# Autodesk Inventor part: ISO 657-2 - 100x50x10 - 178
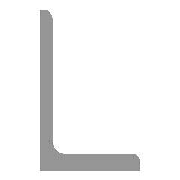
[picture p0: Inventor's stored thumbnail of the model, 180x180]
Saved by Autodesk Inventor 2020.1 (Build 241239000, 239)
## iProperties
Created: 2019-01
Part Number: ISO 657-2 - 100x50x10 - 178
Material: Stahl, weich
Description: Warm gewalzter Winkelstahl, ungleichschenklig
Document SubType Name: Modeling
Standard: ISO
Designer: lutzd
Standard Revision: First edition 1989-08-01
Standards Organization: ISO
Language: de-DE
Size Designation: 100x50x10
Categories: <MemberInstance><Categories><Category DisplayName="Profile" InternalName="089c4875-fa83-4c05-b084-43b9cc11f5ed" Mnemonic="GRDR"><CategoryParameter DisplayName="
Stock Number: 100x50x10
Mass: 1892.4 g
Surface Area: 556.811 cm^2
Volume: 241.07 cm^3
Density: 7.85 g/cm^3
Appearance: Semi-Polished(8)
_CCFamilyMember: 35
_CCFamilyDisplayName: ISO 657/2 - 1989 - Warm gewalzter Winkelstahl, ungleichschenklig
_FrameMemberDoc: Frame Member File
_Version: 15.0.0
_GetPNFromCC: 1
G_L: 178,000 mm
G_W: 50,000 mm
G_H: 100,000 mm
DocNumber: ADSK-014321
Folder: .
Dimensions: 50x100x178 mm
Mass: 1,892 kg
IsCustomPart: 1
Title: Profil-Bauteil
Author: lutzd
Revision Number: -
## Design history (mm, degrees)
node "Startebene"
node "Endebene"
sketch "Skizze"
  geometry: L1 (57.6, -26.8)-(30.1, -26.8); L2 (12.1, -36.8)-(62.1, -36.8); L3 (62.1, -36.8)-(62.1, -31.3); L4 (-7.041, 0)-(21.538, 0); L5 (22.1, -18.8)-(22.1, 58.7); L6 (12.1, 63.2)-(12.1, -36.8); L7 (17.6, 63.2)-(12.1, 63.2); L8 (0, -8.041)-(0, 34.538); L9 (0, 84.318)-(0, -56.986) reference; L10 (-21.056, 0)-(77.047, 0) reference; A1 r 8 centre (30.1, -18.8) between (22.1, -18.8) and (30.1, -26.8); A2 r 4.5 centre (57.6, -31.3) between (62.1, -31.3) and (57.6, -26.8); A3 r 4.5 centre (17.6, 58.7) between (22.1, 58.7) and (17.6, 63.2); 3 further points
  constraints: 16 end point, 6 point on circle, 6 point on line, 6 tangent, 3 centre point, 2 collinear, 2 parallel, 1 equal radius
  dimensions: "d12" = 10 distance between parallel lines of L5 L6 (= G_T); "d13" = 100 distance of L6.start L2.start (= G_H); "d14" = 50 distance of L2.start L2.end (= G_W); "d15" = 36.8 distance between parallel lines of L4 L2 (= ex); "d16" = 10 distance between parallel lines of L2 L1 (= G_T); "d17" = 12.1 distance between parallel lines of L8 L6 (= ey); "d18" = 8 radius of A1 (= G_IR); "d19" = 4.5 radius of A2 (= G_ER)
extrude "Körper" new body sketch "Skizze" stored distance "d4" = 178 (= G_L); taper "d5" = 0 deg
node "Driven Length"
  sketch "Sketch3"
    geometry: L1 (0, 0)-(10, 0) reference
    constraints: 2 end point, 1 horizontal
  workplane "Work Plane3"
  sketch "Sketch4"
    geometry: L1 (-2, 0)-(12, 0) reference; L2 (-2, 178)-(12, 178) reference
    dimensions: "d23" = 178 distance between parallel lines of L1 L2 (derived)
sketch "Skizze5"
  geometry: L1 (25.5, 66)-(25.5, 48); L2 (21, 66)-(21, 48); L3 (30, 48)-(30, 66); L4 (152.5, 20)-(152.5, 2); L5 (148, 20)-(148, 2); L6 (157, 2)-(157, 20); L7 (152.5, 66)-(152.5, 48); L8 (148, 66)-(148, 48); L9 (157, 48)-(157, 66); L10 (25.5, 20)-(25.5, 2); L11 (21, 20)-(21, 2); L12 (30, 2)-(30, 20); L13 (152.5, 57)-(25.5, 57); L14 (152.5, 11)-(25.5, 11); L15 (178, 82)-(0, 82) reference; A1 r 4.5 centre (25.5, 66) between (30, 66) and (21, 66); A2 r 4.5 centre (25.5, 48) between (21, 48) and (30, 48); A3 r 4.5 centre (152.5, 20) between (157, 20) and (148, 20); A4 r 4.5 centre (152.5, 2) between (148, 2) and (157, 2); A5 r 4.5 centre (152.5, 66) between (157, 66) and (148, 66); A6 r 4.5 centre (152.5, 48) between (148, 48) and (157, 48); A7 r 4.5 centre (25.5, 20) between (30, 20) and (21, 20); A8 r 4.5 centre (25.5, 2) between (21, 2) and (30, 2); 4 further points
  constraints: 36 end point, 16 point on circle, 16 tangent, 8 centre point, 7 midpoint, 4 parallel, 4 vertical, 2 collinear, 2 horizontal alignment, 2 vertical alignment
  dimensions: "d24" = 9 distance between parallel lines of L2 L3; "d25" = 18 distance of L1.start L1.end (= d31); "d26" = 9 distance between parallel lines of L5 L6; "d27" = 18 distance of L4.start L4.end (= d31); "d28" = 9 distance between parallel lines of L8 L9; "d29" = 18 distance of L7.start L7.end (= d31); "d30" = 9 distance between parallel lines of L11 L12; "d31" = 18 distance of L10.start L10.end; "d32" = 127 distance between parallel lines of L1 L7; "d33" = 16 distance from line of L15 L7.start; "d34" = 46 distance of L14.start L13.start
extrude "Extrusion2" cut sketch "Skizze5" extent not by distance; stored distance "d35" = 10; taper "d37" = 0 deg; dims "d36" = 5, "d38" = 0
workpoint "Arbeitspunkt1"
workpoint "Arbeitspunkt2"
workpoint "Arbeitspunkt3"
workpoint "Arbeitspunkt4"
workaxis "Arbeitsachse1"
workaxis "Arbeitsachse2"
workaxis "Arbeitsachse3"
workaxis "Arbeitsachse4"
body "Solid1"
other parameters: "G_W" = 50 [user parameter; used in 1 equation term], "G_H" = 100 [user parameter; used in 1 equation term], "G_T" = 10 [user parameter; used in 2 equation terms], "G_ER" = 4.5 [user parameter; used in 1 equation term], "G_IR" = 8 [user parameter; used in 1 equation term], "G_L" = 178 (= d23) [user parameter; used in 1 equation term], "ex" = 36.8 [user parameter; used in 1 equation term], "ey" = 12.1 [user parameter; used in 1 equation term], "G_OFFSET_START" = 0 [user parameter; used in 1 equation term], "G_OFFSET_END" = 0 [user parameter; used in 1 equation term], "d20" = 0 (computed from G_OFFSET_START), "d21" = 178 (= G_OFFSET_END + B_L), "B_L" = 178 [user parameter; used in 1 equation term], "d22" = 90 deg
